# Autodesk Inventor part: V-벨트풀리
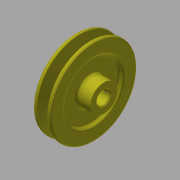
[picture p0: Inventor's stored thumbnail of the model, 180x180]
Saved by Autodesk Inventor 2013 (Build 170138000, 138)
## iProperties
Created: 2015-09
Part Number: V-벨트풀리
Material: 강철, 연강
Document SubType Name: Modeling
Designer: mduedu
Density: 7.86 g/cm^3
Mass: 779.014 g
Surface Area: 277.465 cm^2
Volume: 99.1112 cm^3
Author: mduedu
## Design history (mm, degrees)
sketch "스케치1"
  geometry: L1 (-10, 0)-(10, 0); L2 (-10, 0)-(-10, 48); L3 (-10, 48)-(-5.976, 48); L4 (-5.976, 48)-(-2.154, 35.5); L5 (-2.154, 35.5)-(2.154, 35.5); L6 (2.154, 35.5)-(5.976, 48); L7 (5.976, 48)-(10, 48); L8 (10, 48)-(10, 0); L9 (0, 0)-(0, 35.5); L10 (-10, 43.5)-(10, 43.5); 3 further points
  constraints: 20 end point, 6 point on line, 3 perpendicular, 2 midpoint, 2 parallel, 2 symmetric about line, 1 coincident, 1 collinear, 1 equal length, 1 horizontal, 1 vertical, 1 vertical alignment
  dimensions: "d0" = 20 distance between parallel lines of L8 L2; "d2" = 96 diameter of L3 L1; "d3" = 87 diameter of L10 L1; "d4" = 4.5 distance between parallel lines of L10 L3 (derived); "d5" = 8 distance between parallel lines of L5 L10; "d6" = 9.2 distance of point (4.6, 43.5) point (-4.6, 43.5); "d7" = 34 deg angle of L6 L4
revolve "회전1" sketch "스케치1" stored, may be unused: angle "d8" = 90 deg
sketch "스케치2"
  geometry: C1 r 15 at (0, 0); 1 further point
  constraints: 1 centre point, 1 coincident
  dimensions: "d9" = 30 diameter of C1
extrude "돌출1" join sketch "스케치2" distance "d10" = 11; taper "d11" = 0 deg
fillet "모깎기1" dims "d12" = 1, "d13" = 0.5, "d14" = 2
sketch "스케치3"
  geometry: C1 r 15 at (0, 0) reference; C2 r 32 at (0, 0); 1 further point
  constraints: 1 centre point, 1 coincident
  dimensions: "d15" = 64 diameter of C2
extrude "돌출2" cut sketch "스케치3" distance "d16" = 4; taper "d17" = 0 deg
fillet "모깎기2" dims "d18" = 3
fillet "모깎기3" dims "d19" = 3
fillet "모깎기4" dims "d20" = 3
sketch "스케치4"
  geometry: C1 r 7.5 at (0, 0); 1 further point
  constraints: 1 centre point, 1 coincident
  dimensions: "d21" = 15 diameter of C1
extrude "돌출3" cut sketch "스케치4" stored distance "d22" = 4; taper "d23" = 0 deg
sketch "스케치5"
  geometry: L1 (-2.5, 7.071)-(2.5, 7.071); L2 (2.5, 7.071)-(2.5, 9.8); L3 (2.5, 9.8)-(-2.5, 9.8); L4 (-2.5, 9.8)-(-2.5, 7.071); A1 r 7.5 centre (0, 0) between (-2.5, 7.071) and (2.5, 7.071) reference; 2 further points
  constraints: 8 end point, 3 point on circle, 2 parallel, 1 horizontal, 1 perpendicular, 1 vertical alignment
  dimensions: "d24" = 5 distance of L2.end L3.end; "d26" = 17.3 distance from line of L3 point (0, -7.5)
extrude "돌출4" cut sketch "스케치5" stored distance "d27" = 4; taper "d28" = 0 deg
chamfer "모따기1" distance "d29" = 1; stored, may be unused: second distance "d30" = 2, angle "d31" = 45 deg
node "작업 평면1"
sketch "스케치6"
  geometry: L1 (-11, 15)-(-11, -15) reference; 2 further points
  constraints: 1 horizontal alignment
  dimensions: "d32" = 5 distance from line of point (-6, 0) L1
hole "구멍1" sketch "스케치6" at (-6, 0) diameter "d33" = 3.242; stored, may be unused: countersink angle "d37" = 90 deg, drill point angle "d39" = 118 deg; dims "d34" = 6, "d35" = 4, "d36" = 2, "d38" = 8
node "솔리드1"
mirror "대칭1"
